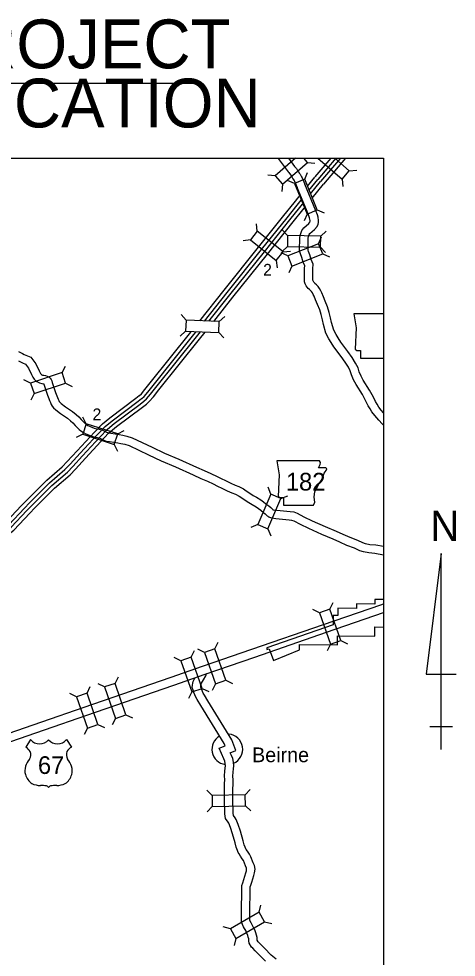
# Model space of a CAD drawing. Extents: x 8749 to 11879, y 13275 to 15339.
# Drawn here: x 9240 to 9553, y 14666 to 15339 of the extents above; entities that cross this region are included whole.
import ezdxf

# ---------------------------------------------------------------- set-up
doc = ezdxf.new("R2010")
doc.units = 0
for name, color, linetype in [('Level 10', 7, 'Continuous'), ('Level 15', 7, 'Continuous'), ('Level 19', 7, 'Continuous'), ('Level 20', 7, 'Continuous'), ('Level 21', 7, 'Continuous'), ('Level 22', 7, 'Continuous'), ('Level 24', 7, 'Continuous'), ('Level 6', 7, 'Continuous'), ('R_Draft', 7, 'Continuous')]:
    doc.layers.add(name, color=color, linetype=linetype)

msp = doc.modelspace()

# ---------------------------------------------------------------- linework, layer by layer
at = {"layer": 'Level 10'}
for points in [[(9425.51, 15238.52), (9425.61, 15238.38), (9432.77, 15228.89), (9433.23, 15228.36), (9433.88, 15227.52), (9434.68, 15226.42), (9435.1, 15225.81), (9435.7, 15224.76), (9436.28, 15223.9), (9437.09, 15222.56), (9437.29, 15222.06), (9439.33, 15217.57)], [(9433.03, 15238.52), (9437.45, 15232.66), (9437.88, 15232.16), (9438.68, 15231.12), (9439.58, 15229.88), (9440.18, 15229.01), (9440.79, 15227.95), (9441.34, 15227.13), (9442.48, 15225.25), (9442.81, 15224.43), (9444.8, 15220.05)], [(9501.21, 15056.01), (9499.48, 15057.96), (9497.86, 15060.12), (9496.62, 15062.21), (9495.42, 15064.15), (9493.92, 15067.25), (9491.18, 15072.34), (9486.64, 15079.44), (9485.08, 15082.3), (9483.77, 15085.41), (9482.85, 15088.39), (9481.17, 15091.78), (9478.62, 15095.83), (9475.64, 15099.95), (9470.55, 15106.81), (9468.59, 15109.86), (9467.1, 15112.21), (9465.46, 15115.47), (9463.87, 15120.86), (9463.21, 15124.08), (9462.27, 15128.04), (9461.08, 15132.05), (9459.29, 15136.12), (9458.07, 15139.25), (9456.93, 15142.04), (9456.21, 15143.66), (9455.31, 15145.28), (9454.34, 15146.73), (9453.15, 15147.96), (9452.02, 15148.89), (9451.58, 15149.33), (9451.25, 15149.74), (9450.89, 15150.25), (9450.65, 15150.76), (9450.54, 15151.1), (9450.5, 15152.69), (9450.5, 15157.61), (9450.61, 15159.38), (9450.72, 15162.55), (9449.29, 15166.08), (9448.23, 15169.44), (9447.31, 15171.76), (9447.07, 15172.75), (9447.26, 15181.32), (9447.44, 15182.55), (9447.9, 15183.89), (9448.44, 15184.59), (9451.79, 15187.58), (9453.64, 15189.63), (9454.2, 15191.41), (9454.44, 15192.45), (9454.57, 15193.98), (9454.3, 15196.3), (9453.73, 15197.97), (9452.66, 15200.9), (9444.84, 15219.95)], [(9501.21, 15047.28), (9500.08, 15048.35), (9497.82, 15050.78), (9494.83, 15054.17), (9492.87, 15056.77), (9491.49, 15059.1), (9490.15, 15061.25), (9488.57, 15064.52), (9486.01, 15069.3), (9481.47, 15076.38), (9479.67, 15079.69), (9478.13, 15083.35), (9477.26, 15086.16), (9475.93, 15088.85), (9473.65, 15092.47), (9470.8, 15096.41), (9465.62, 15103.4), (9463.53, 15106.63), (9461.87, 15109.25), (9459.85, 15113.26), (9458.05, 15119.41), (9457.35, 15122.78), (9456.47, 15126.5), (9455.43, 15129.99), (9453.75, 15133.81), (9452.5, 15137.02), (9451.4, 15139.69), (9450.84, 15140.98), (9450.18, 15142.14), (9449.64, 15142.96), (9449.08, 15143.54), (9447.99, 15144.43), (9447.09, 15145.33), (9446.44, 15146.15), (9445.69, 15147.22), (9445.07, 15148.51), (9444.56, 15150.08), (9444.5, 15152.62), (9444.5, 15157.8), (9444.62, 15159.68), (9444.68, 15161.48), (9443.64, 15164.05), (9442.57, 15167.43), (9441.58, 15169.94), (9441.06, 15172.1), (9441.27, 15181.81), (9441.58, 15183.96), (9442.54, 15186.76), (9444.01, 15188.69), (9447.55, 15191.85), (9448.31, 15192.68), (9448.41, 15193), (9448.5, 15193.4), (9448.54, 15193.88), (9448.42, 15194.96), (9448.07, 15195.97), (9447.06, 15198.73), (9439.29, 15217.67)], [(9239.56, 15100.15), (9242.56, 15098.62), (9243.78, 15097.92), (9244.88, 15097.45), (9248.55, 15095.99)], [(9239.71, 15093.34), (9241.08, 15092.55), (9242.58, 15091.9), (9244.78, 15091.03)], [(9248.55, 15095.99), (9252.12, 15091.27), (9254.38, 15086.12), (9255.08, 15084.72), (9255.46, 15084.2), (9255.85, 15083.79), (9256.01, 15083.67), (9256.91, 15083.2), (9257.7, 15083), (9259.11, 15082.76), (9260.31, 15082.38), (9261.35, 15081.81), (9262.24, 15080.99), (9263.05, 15079.89), (9263.48, 15078.99), (9263.83, 15077.93), (9266.2, 15070.75), (9267.16, 15068.34), (9267.55, 15067.09), (9268.08, 15065.79), (9268.46, 15064.87), (9268.8, 15064.32), (9269.15, 15063.88), (9270.28, 15062.9), (9273.39, 15060.38), (9278.38, 15057.09), (9280.98, 15054.92), (9282.84, 15053.13), (9284.55, 15051.23), (9287.16, 15048.71), (9287.99, 15047.98), (9289.23, 15047.12), (9290.43, 15046.5), (9292.16, 15045.8), (9293.96, 15045.08), (9295.79, 15044.67), (9297.39, 15044.39), (9299.2, 15043.95), (9301.06, 15043.17), (9302.79, 15042.27), (9304.16, 15041.71), (9305.72, 15041.43), (9308.89, 15041.11), (9311.84, 15040.59), (9314.31, 15040.09), (9317.28, 15039.43), (9320.99, 15038.28), (9335.4, 15031.54), (9344.33, 15027.19), (9354.5, 15023.03), (9367.22, 15017.07), (9372.66, 15014.69), (9377.53, 15012.69), (9381.87, 15010.55), (9384.94, 15009), (9387.96, 15007.56), (9391.73, 15005.68), (9394.84, 15004.35), (9397.52, 15003.32), (9400.79, 15001.58), (9402.85, 15000.26), (9405.43, 14998.55), (9407.84, 14996.98), (9410.08, 14995.67), (9413.3, 14993.67), (9415.14, 14992.35), (9416.83, 14991.01), (9418.88, 14989.47), (9420.36, 14988.31), (9422.28, 14986.32)], [(9244.78, 15091.03), (9246.91, 15088.21), (9248.94, 15083.59), (9249.94, 15081.57), (9250.86, 15080.34), (9251.81, 15079.33), (9252.78, 15078.58), (9254.75, 15077.57), (9256.45, 15077.13), (9257.69, 15076.92), (9257.82, 15076.88), (9257.87, 15076.8), (9257.9, 15076.75), (9258.13, 15076.05), (9260.56, 15068.7), (9261.5, 15066.33), (9261.9, 15065.06), (9262.53, 15063.5), (9263.1, 15062.15), (9263.87, 15060.87), (9264.82, 15059.69), (9266.44, 15058.29), (9269.84, 15055.53), (9274.8, 15052.27), (9276.98, 15050.45), (9278.52, 15048.96), (9280.23, 15047.06), (9283.1, 15044.29), (9284.29, 15043.24), (9286.12, 15041.98), (9287.91, 15041.04), (9289.92, 15040.23), (9292.19, 15039.32), (9294.62, 15038.79), (9296.15, 15038.51), (9297.32, 15038.23), (9298.52, 15037.73), (9300.26, 15036.82), (9302.47, 15035.92), (9304.89, 15035.49), (9308.06, 15035.17), (9310.72, 15034.69), (9313.07, 15034.22), (9315.73, 15033.63), (9318.82, 15032.67), (9332.82, 15026.13), (9341.87, 15021.71), (9352.09, 15017.53), (9364.75, 15011.61), (9370.31, 15009.17), (9375.06, 15007.21), (9379.19, 15005.18), (9382.29, 15003.61), (9385.33, 15002.17), (9389.21, 15000.23), (9392.59, 14998.79), (9395.02, 14997.85), (9397.76, 14996.39), (9399.58, 14995.23), (9402.13, 14993.53), (9404.69, 14991.88), (9406.98, 14990.53), (9409.97, 14988.68), (9411.52, 14987.56), (9413.16, 14986.26), (9415.23, 14984.7), (9416.34, 14983.84), (9417.95, 14982.16)], [(9501.21, 14960.3), (9495.65, 14961.25), (9491.35, 14961.63), (9488.28, 14962.25), (9486.42, 14962.87), (9482.66, 14964.7), (9477.13, 14966.72), (9472.21, 14968.92), (9467.42, 14971.05), (9459.46, 14974.32), (9450.26, 14978.59), (9444.29, 14981.4), (9439.59, 14983.89), (9437.06, 14984.82), (9434.18, 14985.24), (9424.77, 14986.11), (9422.43, 14986.45), (9421.96, 14986.61)], [(9501.21, 14954.21), (9494.88, 14955.29), (9490.49, 14955.68), (9486.73, 14956.44), (9484.16, 14957.29), (9480.3, 14959.17), (9474.88, 14961.16), (9469.77, 14963.44), (9465.05, 14965.54), (9457.06, 14968.82), (9447.72, 14973.16), (9441.6, 14976.03), (9437.14, 14978.39), (9435.57, 14978.97), (9433.47, 14979.28), (9424.07, 14980.15), (9421.03, 14980.59), (9419.01, 14981.27), (9418.23, 14981.91)], [(9387.99, 14765.34), (9387.47, 14768.73), (9387.5, 14771.66), (9387.3, 14776.3), (9387.18, 14782.61), (9387.29, 14786.02), (9387.34, 14790.51), (9387.36, 14793.12), (9387.28, 14795.97), (9387.54, 14799.21), (9387.81, 14801.51), (9387.89, 14803.26), (9387.82, 14804.83), (9387.4, 14806.39), (9386.63, 14808.14), (9383.39, 14815.88), (9387.68, 14817.55), (9387.06, 14819.25), (9370.29, 14846.5), (9367.64, 14850.64), (9366.62, 14852.44), (9365.9, 14854.1), (9365.32, 14855.68), (9364.67, 14857.35), (9364.17, 14859.29), (9364.27, 14860.9), (9364.49, 14862.34), (9364.85, 14863.6), (9365.43, 14865.07), (9366.07, 14866.16)], [(9393.7, 14767.67), (9393.47, 14769.15), (9393.5, 14771.76), (9393.29, 14776.49), (9393.18, 14782.56), (9393.29, 14785.88), (9393.33, 14790.45), (9393.36, 14793.17), (9393.29, 14795.81), (9393.51, 14798.63), (9393.79, 14801.02), (9393.9, 14803.24), (9393.79, 14805.76), (9393.08, 14808.39), (9392.15, 14810.5), (9391.3, 14812.52), (9395.34, 14814.1), (9392.48, 14821.89), (9375.37, 14849.69), (9372.78, 14853.73), (9372, 14855.11), (9371.48, 14856.32), (9370.94, 14857.81), (9370.39, 14859.21), (9370.22, 14859.86), (9370.25, 14860.26), (9370.36, 14861.06), (9370.54, 14861.66), (9370.85, 14862.44), (9372.16, 14864.71), (9373.76, 14867.61), (9374.06, 14868.14), (9374.42, 14869.02), (9374.46, 14869.24)], [(9416.65, 14663.08), (9411.5, 14668.26), (9409.31, 14670.58), (9407.55, 14672.41), (9406.65, 14673.28), (9405.01, 14676.17), (9404.71, 14677.66), (9404.57, 14679.15), (9404.29, 14680.44), (9404, 14681.61), (9403.34, 14683.25), (9402.73, 14684.58), (9400.83, 14687.84), (9399.45, 14691.14), (9399.43, 14694.72), (9399.31, 14700.78), (9399.58, 14712.31), (9399.61, 14714.43), (9399.72, 14717.44), (9400.24, 14719.35), (9400.99, 14721.67), (9402.42, 14726.45), (9402.94, 14727.98), (9403.09, 14728.95), (9402.88, 14729.84), (9402.24, 14731.47), (9400.77, 14735.27), (9399.97, 14736.6), (9398.73, 14738.48), (9397.63, 14740.02), (9397.05, 14741.11), (9396.46, 14742.43), (9395.55, 14744.74), (9394.8, 14747.89), (9392.99, 14754.44), (9391.41, 14759.03), (9390.21, 14762.08), (9389.83, 14762.77), (9387.99, 14765.34)], [(9424.31, 14664.56), (9420.7, 14667.52), (9415.82, 14672.43), (9413.66, 14674.72), (9411.8, 14676.64), (9411.45, 14676.99), (9410.7, 14678.3), (9410.65, 14678.54), (9410.51, 14680.08), (9410.14, 14681.78), (9409.73, 14683.45), (9408.85, 14685.63), (9408.06, 14687.35), (9406.21, 14690.53), (9405.44, 14692.36), (9405.43, 14694.79), (9405.31, 14700.77), (9405.58, 14712.2), (9405.61, 14714.28), (9405.69, 14716.52), (9405.99, 14717.63), (9406.72, 14719.89), (9408.14, 14724.62), (9408.8, 14726.55), (9409.19, 14729.19), (9408.63, 14731.61), (9407.84, 14733.64), (9406.18, 14737.92), (9405.05, 14739.8), (9403.67, 14741.89), (9402.73, 14743.19), (9402.45, 14743.73), (9402, 14744.75), (9401.29, 14746.55), (9400.61, 14749.38), (9398.73, 14756.22), (9397.04, 14761.11), (9395.65, 14764.63), (9394.92, 14765.97), (9393.7, 14767.67)]]:
    msp.add_lwpolyline(points, dxfattribs=at)
at = {"layer": 'Level 15'}
for points in [[(9250.18, 14832.47), (9292.81, 14847.28), (9349.03, 14866.69), (9371.52, 14874.53), (9406.88, 14886.79), (9458.22, 14904.49), (9499.27, 14918.63), (9501.21, 14919.32)], [(9252.15, 14826.8), (9294.77, 14841.61), (9350.99, 14861.02), (9373.49, 14868.86), (9408.84, 14881.12), (9460.18, 14898.82), (9501.21, 14912.95)], [(9082.3, 14774.19), (9134.08, 14792.01), (9179.01, 14807.86), (9203.08, 14816.22), (9250.19, 14832.47)], [(9084.43, 14768.58), (9136.06, 14786.34), (9180.99, 14802.2), (9205.04, 14810.55), (9252.15, 14826.8)]]:
    msp.add_lwpolyline(points, dxfattribs=at)
at = {"layer": 'Level 19'}
for points in [[(9463.44, 15238.52), (9451.98, 15225.2)], [(9467.06, 15238.52), (9454.07, 15223.41)], [(9470.36, 15238.52), (9455.97, 15221.78)], [(9473.99, 15238.52), (9458.05, 15219.98)], [(9446.64, 15218.53), (9451.9, 15225.09)], [(9447.73, 15215.49), (9454.04, 15223.37)], [(9448.89, 15212.94), (9455.99, 15221.81)], [(9450.05, 15210), (9458.14, 15220.09)], [(9429.74, 15197.42), (9437.09, 15206.61), (9440.7, 15211.12)], [(9432.03, 15195.88), (9439.23, 15204.9), (9442.06, 15208.42)], [(9434.12, 15194.49), (9441.19, 15203.33), (9443.1, 15205.72)], [(9436.41, 15192.95), (9443.33, 15201.62), (9444.26, 15202.77)], [(9369.54, 15121.99), (9387.03, 15143.99), (9411.69, 15174.83), (9429.74, 15197.42)], [(9372.96, 15121.88), (9389.18, 15142.27), (9413.84, 15173.11), (9432.03, 15195.88)], [(9376.02, 15121.72), (9391.13, 15140.71), (9415.79, 15171.55), (9434.12, 15194.49)], [(9379.47, 15121.63), (9393.28, 15139), (9417.94, 15169.83), (9436.41, 15192.95)], [(9326.06, 15068.44), (9326.24, 15068.57), (9327.66, 15069.81), (9330.23, 15072.76), (9333.9, 15077.52), (9363.12, 15113.93), (9363.44, 15114.33)], [(9327.84, 15066.33), (9327.97, 15066.42), (9329.61, 15067.86), (9332.35, 15071.01), (9336.06, 15075.81), (9365.27, 15112.21), (9366.82, 15114.16)], [(9329.4, 15064.37), (9329.54, 15064.48), (9331.38, 15066.09), (9334.29, 15069.43), (9338.03, 15074.27), (9367.22, 15110.65), (9369.96, 15114.09)], [(9331.36, 15062.41), (9333.34, 15064.15), (9336.41, 15067.68), (9340.19, 15072.57), (9369.37, 15108.93), (9373.32, 15113.9)], [(9294.17, 15042.36), (9299.86, 15048.23), (9304.99, 15052.52), (9323.62, 15066.63), (9326.06, 15068.44)], [(9296.17, 15040.47), (9301.74, 15046.21), (9306.71, 15050.37), (9325.27, 15064.43), (9327.84, 15066.33)], [(9297.98, 15038.75), (9303.44, 15044.38), (9308.26, 15048.41), (9326.76, 15062.43), (9329.4, 15064.37)], [(9304.24, 15041.46), (9309.98, 15046.26), (9328.41, 15060.23), (9331.26, 15062.33), (9331.36, 15062.41)], [(9245.65, 14993.64), (9260.03, 15007.93), (9271.03, 15017.42), (9274.63, 15021.25), (9281.77, 15028.97), (9294.17, 15042.36)], [(9247.59, 14991.69), (9261.89, 15005.91), (9272.93, 15015.43), (9276.64, 15019.37), (9283.79, 15027.1), (9296.17, 15040.47)], [(9249.35, 14989.92), (9263.59, 15004.08), (9274.67, 15013.62), (9278.47, 15017.67), (9285.62, 15025.41), (9297.98, 15038.75)], [(9251.29, 14987.97), (9265.46, 15002.06), (9276.57, 15011.63), (9280.48, 15015.8), (9287.64, 15023.54), (9304.24, 15041.46)], [(9109.92, 14870.66), (9124.94, 14884.43), (9151.41, 14908.53), (9170.43, 14926.73), (9187.67, 14941.52), (9203.82, 14956.17), (9218.94, 14969.62), (9226.41, 14974.36), (9230.86, 14977.96), (9241.9, 14989.81), (9245.61, 14993.6)], [(9111.83, 14868.69), (9126.79, 14882.4), (9153.28, 14906.52), (9172.28, 14924.69), (9189.49, 14939.46), (9205.66, 14954.13), (9220.6, 14967.41), (9228.02, 14972.12), (9232.74, 14975.94), (9243.89, 14987.91), (9247.58, 14991.68)], [(9113.46, 14866.79), (9128.48, 14880.55), (9154.99, 14904.7), (9173.96, 14922.84), (9191.14, 14937.58), (9207.33, 14952.27), (9222.11, 14965.41), (9229.48, 14970.09), (9234.45, 14974.11), (9245.7, 14986.18), (9249.37, 14989.93)], [(9115.34, 14864.79), (9130.33, 14878.52), (9156.86, 14902.69), (9175.8, 14920.8), (9192.96, 14935.52), (9209.17, 14950.22), (9223.77, 14963.21), (9231.09, 14967.85), (9236.33, 14972.09), (9247.69, 14984.28), (9251.33, 14988.01)]]:
    msp.add_lwpolyline(points, dxfattribs=at)
at = {"layer": 'Level 20'}
for p, q in [((9446.75, 15235.46), (9452.01, 15235.06)), ((9423.57, 15225.98), (9418.3, 15226.38)), ((9444.66, 15223.49), (9446.7, 15228.36)), ((9476.63, 15229.51), (9481.9, 15229.91)), ((9428.73, 15219.97), (9428.33, 15214.71)), ((9437.33, 15220.49), (9432.46, 15222.52)), ((9471.47, 15223.51), (9471.87, 15218.24)), ((9453.67, 15201.51), (9458.54, 15199.47)), ((9446.35, 15198.5), (9444.31, 15193.63)), ((9410.72, 15186.23), (9410.13, 15191.47)), ((9432.42, 15183.24), (9428.77, 15187.05)), ((9456.17, 15182.71), (9459.99, 15186.36)), ((9405.77, 15180.04), (9400.53, 15179.45)), ((9454.65, 15177.34), (9456.76, 15182.18)), ((9432.24, 15175.32), (9428.43, 15171.67)), ((9456, 15174.79), (9459.65, 15170.98)), ((9432.56, 15168.61), (9427.71, 15170.71)), ((9429.28, 15171.4), (9434.53, 15171.98)), ((9457.56, 15169.97), (9462.41, 15167.87)), ((9424.34, 15165.21), (9424.92, 15159.96)), ((9435.46, 15161.24), (9433.36, 15156.4)), ((9359.72, 15122.62), (9356.15, 15126.51)), ((9383.45, 15121.58), (9387.35, 15125.15)), ((9359.37, 15114.71), (9355.48, 15111.14)), ((9383.11, 15113.67), (9386.68, 15109.78)), ((9270.87, 15084.9), (9273.23, 15089.62)), ((9248.32, 15077.4), (9243.6, 15079.77)), ((9273.37, 15077.38), (9278.09, 15075.02)), ((9250.82, 15069.89), (9248.45, 15065.17)), ((9288.17, 15048.35), (9285.78, 15053.06)), ((9285.7, 15040.82), (9280.99, 15038.43)), ((9310.75, 15040.95), (9315.46, 15043.34)), ((9308.28, 15033.43), (9310.67, 15028.72)), ((9420.38, 14997.85), (9418.4, 15002.75)), ((9427.66, 14994.75), (9432.56, 14996.72)), ((9411.07, 14975.99), (9406.17, 14974.02)), ((9418.36, 14972.89), (9420.33, 14967.99)), ((9462.79, 14915.45), (9465.1, 14920.2)), ((9455.3, 14912.87), (9450.55, 14915.19)), ((9380.36, 14886.99), (9382.67, 14891.74)), ((9463.04, 14890.41), (9460.72, 14885.66)), ((9470.53, 14892.99), (9475.27, 14890.67)), ((9363.41, 14881.1), (9365.71, 14885.86)), ((9372.88, 14884.4), (9368.13, 14886.7)), ((9355.93, 14878.5), (9351.18, 14880.79)), ((9308.88, 14862.22), (9311.19, 14866.97)), ((9388.15, 14864.55), (9392.9, 14862.24)), ((9288.74, 14855.27), (9291.04, 14860.02)), ((9301.39, 14859.64), (9296.64, 14861.95)), ((9371.23, 14858.67), (9375.98, 14856.37)), ((9380.67, 14861.95), (9378.36, 14857.2)), ((9281.26, 14852.67), (9276.51, 14854.97)), ((9363.75, 14856.06), (9361.45, 14851.31)), ((9309.14, 14837.18), (9306.83, 14832.43)), ((9316.63, 14839.76), (9321.38, 14837.45)), ((9289.06, 14830.23), (9286.76, 14825.48)), ((9296.54, 14832.83), (9301.29, 14830.53)), ((9378.31, 14781.99), (9374.5, 14785.65)), ((9402.06, 14782.44), (9405.72, 14786.25)), ((9378.46, 14774.07), (9374.8, 14770.26)), ((9402.21, 14774.53), (9406.02, 14770.86)), ((9411.97, 14698.29), (9413.32, 14703.4)), ((9415.95, 14691.45), (9421.06, 14690.1)), ((9391.43, 14686.34), (9386.33, 14687.69)), ((9395.42, 14679.49), (9394.07, 14674.39))]:
    msp.add_line(p, q, dxfattribs=at)
for points in [[(9438.16, 15238.52), (9423.57, 15225.98), (9428.73, 15219.97), (9446.75, 15235.46), (9444.12, 15238.52)], [(9454.01, 15238.52), (9471.47, 15223.51), (9476.63, 15229.51), (9466.16, 15238.52)]]:
    msp.add_lwpolyline(points, dxfattribs=at)
for points in [[(9453.67, 15201.51), (9444.66, 15223.49), (9437.33, 15220.49), (9446.35, 15198.5)], [(9429.28, 15171.4), (9410.72, 15186.23), (9405.77, 15180.04), (9424.34, 15165.21)], [(9432.24, 15175.32), (9456, 15174.79), (9456.17, 15182.71), (9432.42, 15183.24)], [(9454.65, 15177.34), (9432.56, 15168.61), (9435.46, 15161.24), (9457.56, 15169.97)], [(9383.45, 15121.58), (9359.72, 15122.62), (9359.37, 15114.71), (9383.11, 15113.67)], [(9270.87, 15084.9), (9248.32, 15077.4), (9250.82, 15069.89), (9273.37, 15077.38)], [(9285.7, 15040.82), (9308.28, 15033.43), (9310.75, 15040.95), (9288.17, 15048.35)], [(9418.36, 14972.89), (9427.66, 14994.75), (9420.38, 14997.85), (9411.07, 14975.99)], [(9470.53, 14892.99), (9462.79, 14915.45), (9455.3, 14912.87), (9463.04, 14890.41)], [(9388.15, 14864.55), (9380.36, 14886.99), (9372.88, 14884.4), (9380.67, 14861.95)], [(9371.23, 14858.67), (9363.41, 14881.1), (9355.93, 14878.5), (9363.75, 14856.06)], [(9316.63, 14839.76), (9308.88, 14862.22), (9301.39, 14859.64), (9309.14, 14837.18)], [(9281.26, 14852.67), (9289.06, 14830.23), (9296.54, 14832.83), (9288.74, 14855.27)], [(9402.06, 14782.44), (9378.31, 14781.99), (9378.46, 14774.07), (9402.21, 14774.53)], [(9395.42, 14679.49), (9415.95, 14691.45), (9411.97, 14698.29), (9391.43, 14686.34)]]:
    msp.add_lwpolyline(points, close=True, dxfattribs=at)
at = {"layer": 'Level 21'}
msp.add_lwpolyline([(9501.21, 15127.17), (9479.91, 15127.18), (9481.43, 15117.03), (9480.75, 15101.64), (9482.11, 15100.79), (9484.64, 15100.79), (9484.64, 15095.38), (9501.21, 15095.38)], dxfattribs=at)
msp.add_lwpolyline([(9424.8, 15021.79), (9426.33, 15011.64), (9425.65, 14996.24), (9427, 14995.39), (9429.54, 14995.39), (9429.54, 14989.98), (9450.86, 14989.98), (9451.87, 14992.18), (9451.53, 14995.73), (9452.04, 14999.79), (9453.9, 15003.01), (9455.09, 15005.38), (9456.78, 15007.91), (9457.79, 15010.62), (9458.64, 15012.82), (9460.16, 15014.68), (9460.5, 15015.87), (9459.82, 15016.71), (9454.58, 15016.71), (9455.76, 15019.08), (9455.93, 15020.6), (9455.23, 15021.77)], close=True, dxfattribs=at)
at = {"layer": 'Level 22'}
for p, q in [((9248.33, 14821.9), (9244.87, 14816.55)), ((9274.07, 14821.9), (9277.53, 14816.55))]:
    msp.add_line(p, q, dxfattribs=at)
for centre, radius, start, end in [((9240.35, 14808.78), 8.99, 30.7809, 59.98827), ((9254.78, 14827.33), 8.42, 220.07504, 319.67012), ((9267.62, 14827.33), 8.42, 220.32988, 319.92496), ((9282.06, 14808.78), 8.99, 120.01173, 149.2191), ((9242.33, 14811.15), 6.17, 328.81046, 21.21077), ((9280.08, 14811.15), 6.17, 158.78923, 211.18954), ((9253.7, 14799.69), 9.5, 160.95764, 197.38186), ((9258.45, 14798.51), 14.38, 138.95648, 162.69135), ((9263.95, 14798.51), 14.38, 17.30865, 41.04352), ((9268.7, 14799.69), 9.5, 342.61814, 19.04236), ((9255.25, 14799.72), 11, 195.10743, 237.13119), ((9267.16, 14799.72), 11, 302.86881, 344.89257), ((9255.45, 14803.18), 14.12, 244.07708, 269.57785), ((9255.78, 14763.2), 25.87, 81.19416, 90.95387), ((9266.62, 14763.2), 25.87, 89.04613, 98.80584), ((9266.95, 14803.18), 14.12, 270.42215, 295.92292), ((9259.01, 14786.39), 2.48, 28.03422, 72.98637), ((9263.39, 14786.39), 2.48, 107.01363, 151.96578)]:
    msp.add_arc(centre, radius, start, end, dxfattribs=at)
at = {"layer": 'Level 24'}
for start, end in [(120.37683, 261.45171), (294.49125, 84.33106)]:
    msp.add_arc((9389.24, 14814.96), 11, start, end, dxfattribs=at)
at = {"layer": 'Level 6'}
for points in [[(9501.21, 14922.35), (9494.86, 14922.4), (9494.86, 14919.1), (9481.66, 14919.22), (9481.66, 14915.92), (9468.36, 14916.04), (9468.32, 14910.83), (9465.05, 14910.88), (9465, 14904.14), (9417.58, 14887.73), (9417.56, 14886.53)], [(9417.56, 14886.53), (9419.25, 14887.08), (9422.36, 14878.52), (9440.96, 14886.21), (9441.01, 14890.16), (9468.16, 14889.8), (9468.21, 14896.4), (9494.9, 14896.07), (9494.9, 14902.67), (9501.21, 14902.61)]]:
    msp.add_lwpolyline(points, dxfattribs=at)
at = {"layer": 'R_Draft'}
for p, q in [((9162.72, 15292.43), (9371.12, 15292.43)), ((9542.4, 14955.32), (9531.6, 14868.92)), ((9542.4, 14814.92), (9542.4, 14955.32)), ((9531.6, 14868.92), (9553.2, 14868.92)), ((9534.25, 14831.32), (9550.45, 14831.32))]:
    msp.add_line(p, q, dxfattribs=at)
msp.add_lwpolyline([(8771.23, 15238.52), (9501.21, 15238.52), (9501.21, 14602.87), (8771.23, 14602.87)], close=True, dxfattribs=at)

# ---------------------------------------------------------------- texts
at = {"layer": 'Level 20'}
for p in [(9414.9, 15154.4), (9292.69, 15050.82)]:
    msp.add_text('2', height=8.45, dxfattribs=at).set_placement(p)
at = {"layer": 'Level 21'}
msp.add_text('182', height=12.672, dxfattribs=at).set_placement((9431.21, 15000.45))
at = {"layer": 'Level 22'}
msp.add_text('67', height=12.672, dxfattribs=at).set_placement((9253.59, 14797.33))
at = {"layer": 'Level 24'}
msp.add_text('Beirne', height=10.56, dxfattribs=at).set_placement((9406.98, 14805.75))
at = {"layer": 'R_Draft'}
for s, height, p in [('PROJECT', 35, (9173.12, 15302.99)), ('LOCATION', 35, (9173.93, 15260.62)), ('N', 21.6, (9534.6, 14964.32))]:
    msp.add_text(s, height=height, dxfattribs=at).set_placement(p)

doc.saveas('drawing.dxf')
